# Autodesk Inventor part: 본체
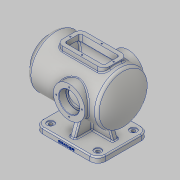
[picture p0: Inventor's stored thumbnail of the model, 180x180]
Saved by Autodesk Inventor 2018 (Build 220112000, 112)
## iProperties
Created: 2021-11
Part Number: 본체
Material: 알루미늄 6061
Document SubType Name: Modeling
Designer: home
Density: 2.7 g/cm^3
Appearance: 알루미늄 - 평지
Mass: 3539.14 g
Surface Area: 2407.45 cm^2
Volume: 1310.79 cm^3
Author: home
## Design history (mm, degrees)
sketch "스케치1"
  geometry: L1 (0, 0)-(210, 0); L2 (0, 32.5)-(0, 47.5); L3 (0, 47.5)-(10, 47.5); L4 (10, 47.5)-(10, 65); L5 (10, 65)-(185.993, 65); L6 (25, 55)-(181.239, 55); L7 (25, 32.5)-(25, 55); L8 (0, 32.5)-(25, 32.5); L9 (200, 0)-(210, 0); A1 r 100 centre (110, 0) between (210, 0) and (185.993, 65); A2 r 90 centre (110, 0) between (200, 0) and (181.239, 55)
  constraints: 18 end point, 5 perpendicular, 4 point on circle, 2 centre point, 1 horizontal, 1 horizontal alignment, 1 parallel, 1 tangent, 1 vertical
  dimensions: "d1" = 210 distance of L1.start L1.end; "d2" = 95 diameter of L3 L1; "d3" = 130 diameter of L5 L1; "d4" = 10 distance of L2.end L3.end; "d5" = 10 radial gap between concentric circles of A1 A2; "d6" = 10 distance between parallel lines of L5 L6; "d7" = 25 distance between parallel lines of L7 L2; "d8" = 65 diameter of L8 L1; "d9" = 90 radius of A2; "d10" = 65 distance from line of L9.start L5
revolve "회전1" sketch "스케치1" stored, may be unused: angle "d11" = 90 deg
node "작업 평면1"
sketch "스케치2"
  geometry: L1 (-30, 65)-(-190, 65); L2 (-190, 65)-(-190, -65); L3 (-190, -65)-(-30, -65); L4 (-30, -65)-(-30, 65); L5 (-30, 65)-(-190, -65); L6 (-190, 65)-(-30, -65); 3 further points
  constraints: 12 end point, 3 midpoint, 2 parallel, 1 horizontal, 1 horizontal alignment, 1 perpendicular
  dimensions: "d13" = 130 distance of L1.end L2.end; "d14" = 160 distance of L1.start L1.end; "d15" = 30 distance from line of point (0, 0) L4
extrude "돌출1" join sketch "스케치2" distance "d16" = 14; taper "d17" = 0 deg
node "작업 평면2"
sketch "스케치4"
  geometry: L1 (0, 14)-(130, 14) reference; L2 (65, 49)-(65, 14); L3 (115, 14)-(98.809, 58.485); L4 (115, 14)-(65, 14); A1 r 65 centre (65, 114) between (65, 49) and (98.809, 58.485); 1 further point
  constraints: 6 end point, 2 point on circle, 1 centre point, 1 coincident, 1 horizontal, 1 midpoint, 1 point on line, 1 vertical
  dimensions: "d22" = 50 distance of L2.end L3.start; "d23" = 110 deg angle of L1 L3; "d24" = 65 radius of A1
extrude "돌출2" join sketch "스케치4" stored distance "d25" = 14; taper "d26" = 0 deg
sketch "스케치5"
  geometry: L1 (190, -100)-(30, -100) reference; L2 (10, -65)-(185.993, -65) reference; L3 (170, -100)-(157.261, -65); L4 (110, -149.8)-(110, 100.8) reference; 1 further point
  constraints: 2 end point, 2 point on line
  dimensions: "d28" = 110 deg angle of L1 L3; "d29" = 60 distance from line of L4 L3.start
feature "리브1" sketch "스케치5" dims "d30" = 1, "d31" = 14, "d32" = 0, "d33" = 0, "d34" = 1, "d35" = 1
node "작업 평면3"
sketch "스케치8"
  geometry: L1 (0, -47.5)-(0, 47.5) reference; C1 r 40 at (127, 0); 1 further point
  constraints: 1 centre point, 1 horizontal alignment
  dimensions: "d41" = 80 diameter of C1; "d42" = 127 distance from line of C1.centre L1
extrude "돌출3" join sketch "스케치8" stored distance "d43" = 14; taper "d44" = 0 deg
sketch "스케치9"
  geometry: C1 r 26 at (0, 0); 1 further point
  constraints: 1 centre point, 1 horizontal alignment
  dimensions: "d45" = 52 diameter of C1; "d46" = 127 distance of point (-127, 0) C1.centre
extrude "돌출4" cut sketch "스케치9" distance "d47" = 18; taper "d48" = 0 deg
sketch "스케치10"
  geometry: C1 r 21 at (0, 0); 1 further point
  constraints: 1 centre point, 1 horizontal alignment
  dimensions: "d49" = 42 diameter of C1; "d50" = 127 distance of point (-127, 0) C1.centre
extrude "돌출5" cut sketch "스케치10" stored distance "d51" = 18; taper "d52" = 0 deg
node "작업 평면4"
sketch "스케치11"
  geometry: L1 (-50, 30)-(-170, 30); L2 (-170, 30)-(-170, -30); L3 (-170, -30)-(-50, -30); L4 (-50, -30)-(-50, 30); L5 (-50, 30)-(-170, -30); L6 (-170, 30)-(-50, -30); L7 (0, 47.5)-(0, -47.5) reference; 3 further points
  constraints: 12 end point, 3 midpoint, 2 parallel, 1 horizontal, 1 horizontal alignment, 1 perpendicular
  dimensions: "d54" = 60 distance of L1.end L2.end; "d55" = 120 distance of L2.end L3.end; "d56" = 50 distance between parallel lines of L7 L4
extrude "돌출6" join sketch "스케치11" stored distance "d57" = 18; taper "d58" = 0 deg
sketch "스케치12"
  geometry: L1 (170, 30)-(50, 30) reference; L2 (170, -30)-(170, 30) reference; L3 (50, -30)-(170, -30) reference; L4 (50, 30)-(50, -30) reference; L5 (60, 20)-(160, 20); L6 (160, 20)-(160, -20); L7 (160, -20)-(60, -20); L8 (60, -20)-(60, 20); 1 further point
  constraints: 8 end point, 3 other
  dimensions: "d59" = 10 distance between parallel lines of L1 L5
extrude "돌출7" cut sketch "스케치12" stored distance "d60" = 18; taper "d61" = 0 deg
sketch "스케치13" dims "d62" = 80
  geometry: C1 r 32.5 at (0, 0) reference; 3 further points
  constraints: 2 vertical alignment, 1 coincident, 2 other
hole "구멍1" sketch "스케치13" at (0, 40) diameter "d63" = 3.242; stored, may be unused: countersink angle "d67" = 90 deg, drill point angle "d69" = 118 deg; dims "d64" = 11, "d65" = 4, "d66" = 2, "d68" = 13
sketch "스케치14" dims "d73" = 65
  geometry: L1 (-127, -47.5)-(-127, 47.5) reference; 3 further points
  constraints: 2 vertical alignment, 1 horizontal alignment, 2 other
  dimensions: "d74" = 127 distance from line of L1 point (0, 0)
hole "구멍2" sketch "스케치14" at (0, 32.5) diameter "d75" = 3.242; stored, may be unused: countersink angle "d79" = 90 deg, drill point angle "d81" = 118 deg; dims "d76" = 11, "d77" = 4, "d78" = 2, "d80" = 13
sketch "스케치15"
  geometry: L1 (50, 30)-(50, -30) reference; L2 (170, -30)-(170, 30) reference; 5 further points
  constraints: 2 horizontal alignment
  dimensions: "d85" = 60 distance from line of L1 point (110, 25); "d86" = 60 distance from line of L1 point (110, -25); "d87" = 5 distance from line of L1 point (55, 0); "d88" = 5 distance from line of L2 point (165, 0); "d89" = 25 vertical distance of point (0, 0) point (110, 25); "d90" = 25 vertical distance of point (0, 0) point (110, -25)
hole "구멍3" sketch "스케치15" at (110, 25), (110, -25), (55, 0), (165, 0) diameter "d91" = 3.242; stored, may be unused: countersink angle "d95" = 90 deg, drill point angle "d97" = 118 deg; dims "d92" = 9, "d93" = 4, "d94" = 2, "d96" = 11
fillet "모깎기1" dims "d98" = 10, "d100" = 15, "d101" = 0.3, "d102" = 20
sketch "스케치16"
  geometry: L1 (190, -45)-(190, 45) reference; L2 (50, -65)-(170, -65) reference; L3 (30, 45)-(30, -45) reference; L4 (170, 65)-(50, 65) reference; C1 r 9 at (50, 45); C2 r 9 at (170, 45); C3 r 9 at (170, -45); C4 r 9 at (50, -45); A1 r 20 centre (50, 45) between (50, 65) and (30, 45) reference; A2 r 20 centre (170, 45) between (190, 45) and (170, 65) reference; A3 r 20 centre (170, -45) between (170, -65) and (190, -45) reference; A4 r 20 centre (50, -45) between (30, -45) and (50, -65) reference; A5 r 20 centre (50, 45) between (50, 65) and (30, 45) reference; 1 further point
  constraints: 4 centre point, 4 coincident, 3 equal radius
  dimensions: "d103" = 18 diameter of C1
extrude "돌출8" cut sketch "스케치16" distance "d104" = 2; taper "d105" = 0 deg
sketch "스케치17"
  geometry: L1 (140, 0)-(140, 90) reference; L2 (0, -20)-(120, -20) reference; L3 (-20, 90)-(-20, 0) reference; L4 (120, 110)-(0, 110) reference; C1 r 4.5 at (0, 90); C2 r 4.5 at (120, 90); C3 r 4.5 at (120, 0); C4 r 4.5 at (0, 0); A1 r 20 centre (120, 90) between (140, 90) and (120, 110) reference; A2 r 20 centre (120, 0) between (120, -20) and (140, 0) reference; A3 r 20 centre (0, 0) between (-20, 0) and (0, -20) reference; A4 r 20 centre (0, 90) between (0, 110) and (-20, 90) reference; 1 further point
  constraints: 4 centre point, 4 coincident, 3 equal radius
  dimensions: "d106" = 9 diameter of C1
extrude "돌출9" cut sketch "스케치17" extent not by distance; stored distance "d107" = 0; taper "d108" = 0 deg
chamfer "모따기1" distance "d110" = 1; stored, may be unused: second distance "d111" = 2, angle "d112" = 45 deg
fillet "모깎기3" dims "d113" = 3
fillet "모깎기4" dims "d124" = 5, "d125" = 3
sketch "스케치18"
  geometry: L1 (0, 0)-(120, 0) reference; L2 (-20, 14)-(-20, 0) reference; 3 further points
  constraints: 1 other
  dimensions: "d115" = 5 distance from line of L1 point (60, 5); "d116" = 80 distance from line of L2 point (60, 5)
feature "엠보싱1" sketch "스케치18" dims "d1" = 210, "d2" = 95, "d3" = 130, "d4" = 10, "d5" = 10, "d6" = 10, "d7" = 25, "d8" = 65, "d9" = 90, "d10" = 65, "d13" = 130, "d14" = 160, "d15" = 30, "d117" = 0.5, "d118" = 0
fillet "모깎기5" dims "d119" = 5, "d120" = 3
fillet "모깎기6" dims "d121" = 3
fillet "모깎기7" dims "d122" = 3
fillet "모깎기8" dims "d126" = 3
node "솔리드1"
mirror "미러1"
mirror "미러2"
mirror "미러3"
pattern_circular "원형 패턴1" dims angle "d71" = 360 deg
pattern_circular "원형 패턴2" dims angle "d83" = 360 deg
mirror "미러4"
node "투영된 루프1"
node "투영된 루프2"
other parameters: "d12" = -114, "d40" = 75
